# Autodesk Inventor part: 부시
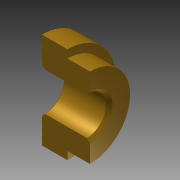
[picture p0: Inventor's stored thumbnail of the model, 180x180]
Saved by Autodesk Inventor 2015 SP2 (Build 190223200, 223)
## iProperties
Created: 2011-04
Part Number: 부시
Document SubType Name: Modeling
Designer: 한국산업디자인학원 [http://gmhk.co.kr]
Density: 1 g/cm^3
Material: 일반
Appearance: 황동 - 새틴
Author: pww
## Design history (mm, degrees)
sketch "스케치1"
  geometry: L1 (0, 0)-(15, 0); L2 (0, 6)-(15, 6); L3 (15, 6)-(15, 12.5); L4 (15, 12.5)-(8, 12.5); L5 (8, 12.5)-(8, 15); L6 (8, 15)-(0, 15); L7 (0, 15)-(0, 6)
  constraints: 14 end point, 4 parallel, 2 vertical alignment, 1 horizontal, 1 perpendicular, 1 vertical
  dimensions: "d0" = 15 distance of L1.start L1.end; "d1" = 12 diameter of L2 L1; "d2" = 25 diameter of L4 L1; "d3" = 8 distance of L5.end L6.end; "d4" = 30 diameter of L6 L1
revolve "회전1" sketch "스케치1" stored, may be unused: angle "d5" = 90 deg
chamfer "모따기1" distance "d6" = 1; stored, may be unused: second distance "d7" = 2, angle "d8" = 45 deg
sketch "스케치2"
  geometry: L1 (36.85, 0)-(-45.437, 0); L2 (-45.437, 0)-(-45.437, -27.715); L3 (-45.437, -27.715)-(36.85, -27.715); L4 (36.85, -27.715)-(36.85, 0); 1 further point
  constraints: 8 end point, 2 parallel, 1 horizontal, 1 perpendicular
extrude "돌출1" cut sketch "스케치2" distance "d9" = 123; taper "d10" = 0 deg
node "솔리드1"
